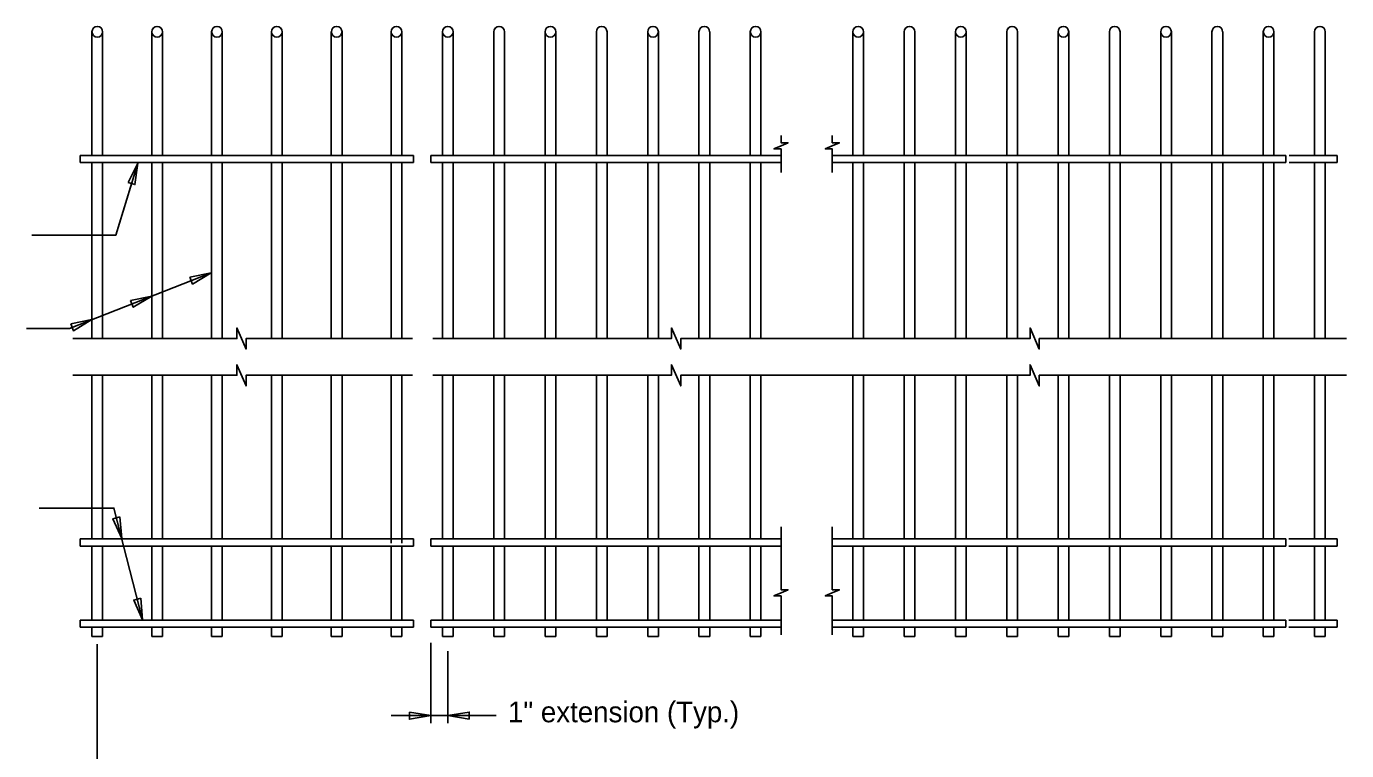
# Model space of a CAD drawing. Extents: x 4.6 to 40.7, y -0.7 to 17.4.
# Drawn here: x 8.02 to 14.45, y 7.29 to 10.82 of the extents above; entities that cross this region are included whole.
import ezdxf

# ---------------------------------------------------------------- set-up
doc = ezdxf.new("R2010")
doc.units = 0
for name, color, linetype in [('Dimension', 7, 'Continuous'), ('Rebar', 7, 'Continuous'), ('Rebar_h', 7, 'Continuous'), ('Symbols', 7, 'Continuous')]:
    doc.layers.add(name, color=color, linetype=linetype)

msp = doc.modelspace()

# ---------------------------------------------------------------- linework, layer by layer
at = {"layer": 'Dimension'}
for p, q in [((8.3629, 6.3332), (8.3629, 7.8082)), ((9.9879, 7.8157), (9.9879, 7.4242)), ((10.0712, 7.7749), (10.0712, 7.4242)), ((9.7947, 7.4608), (10.3061, 7.4608))]:
    msp.add_line(p, q, dxfattribs=at)
for points in [[(11.6949, 10.287), (11.6949, 10.2513), (11.7293, 10.2513), (11.6949, 10.2363), (11.6604, 10.2213), (11.6949, 10.2213), (11.6949, 10.1072)], [(11.9448, 10.287), (11.9448, 10.2513), (11.9793, 10.2513), (11.9448, 10.2363), (11.9104, 10.2213), (11.9448, 10.2213), (11.9448, 10.1072)], [(8.0433, 9.801), (8.4532, 9.801), (8.56, 10.1525)], [(8.0175, 9.347), (8.2271, 9.347), (8.9178, 9.6176)], [(8.0798, 8.4721), (8.4443, 8.4721), (8.5831, 7.9274)], [(11.6949, 8.3812), (11.6949, 8.0739), (11.7293, 8.0739), (11.6949, 8.0589), (11.6604, 8.0439), (11.6949, 8.0439), (11.6949, 7.8542)], [(11.9448, 8.3812), (11.9448, 8.0739), (11.9793, 8.0739), (11.9448, 8.0589), (11.9104, 8.0439), (11.9448, 8.0439), (11.9448, 7.8542)]]:
    msp.add_lwpolyline(points, dxfattribs=at)
for points in [[(8.5128, 10.058), (8.56, 10.1525), (8.5466, 10.0478)], [(8.8144, 9.596), (8.9178, 9.6176), (8.8273, 9.5632)], [(8.5251, 9.4827), (8.6285, 9.5043), (8.538, 9.4499)], [(8.2335, 9.3685), (8.3369, 9.39), (8.2463, 9.3356)], [(8.4734, 8.4285), (8.482, 8.3232), (8.4392, 8.4198)], [(8.5745, 8.0327), (8.5831, 7.9274), (8.5403, 8.024)], [(9.8838, 7.4784), (9.9879, 7.4608), (9.8838, 7.4431)], [(10.1754, 7.4431), (10.0712, 7.4608), (10.1754, 7.4784)]]:
    msp.add_lwpolyline(points, close=True, dxfattribs=at)
at = {"layer": 'Rebar'}
for p, q in [((8.3369, 10.792), (8.3369, 10.1898)), ((8.3889, 10.792), (8.3889, 10.1898)), ((8.6285, 10.792), (8.6285, 10.1898)), ((8.6806, 10.792), (8.6806, 10.1898)), ((8.9202, 10.792), (8.9202, 10.1898)), ((8.9723, 10.792), (8.9723, 10.1898)), ((9.2119, 10.792), (9.2119, 10.1898)), ((9.2639, 10.792), (9.2639, 10.1898)), ((9.5035, 10.792), (9.5035, 10.1898)), ((9.5556, 10.792), (9.5556, 10.1898)), ((9.7952, 10.792), (9.7952, 10.1898)), ((9.8473, 10.792), (9.8473, 10.1898)), ((10.0452, 10.792), (10.0452, 10.1898)), ((10.0973, 10.792), (10.0973, 10.1898)), ((10.5452, 10.792), (10.5452, 10.1898)), ((10.5973, 10.792), (10.5973, 10.1898)), ((11.0452, 10.792), (11.0452, 10.1898)), ((11.0973, 10.792), (11.0973, 10.1898)), ((11.5452, 10.792), (11.5452, 10.1898)), ((11.5973, 10.792), (11.5973, 10.1898)), ((12.0452, 10.792), (12.0452, 10.1898)), ((12.0973, 10.792), (12.0973, 10.1898)), ((12.5452, 10.792), (12.5452, 10.1898)), ((12.5973, 10.792), (12.5973, 10.1898)), ((13.0452, 10.792), (13.0452, 10.1898)), ((13.0973, 10.792), (13.0973, 10.1898)), ((13.5452, 10.792), (13.5452, 10.1898)), ((13.5973, 10.792), (13.5973, 10.1898)), ((14.0452, 10.792), (14.0452, 10.1898)), ((14.0973, 10.792), (14.0973, 10.1898)), ((8.2796, 10.1898), (9.9046, 10.1898)), ((8.2796, 10.1898), (8.2796, 10.1547)), ((9.9046, 10.1898), (9.9046, 10.1547)), ((9.9879, 10.1898), (9.9879, 10.1547)), ((9.9879, 10.1898), (11.6949, 10.1898)), ((11.9448, 10.1898), (14.1546, 10.1898)), ((14.1546, 10.1898), (14.1546, 10.1547)), ((8.2796, 10.1547), (9.9046, 10.1547)), ((8.3369, 10.1547), (8.3369, 9.2976)), ((8.3889, 10.1547), (8.3889, 9.2976)), ((8.6285, 10.1547), (8.6285, 9.2976)), ((8.6806, 10.1547), (8.6806, 9.2976)), ((8.9202, 10.1547), (8.9202, 9.2976)), ((8.9723, 10.1547), (8.9723, 9.2976)), ((9.2119, 10.1547), (9.2119, 9.2976)), ((9.2639, 10.1547), (9.2639, 9.2976)), ((9.5035, 10.1547), (9.5035, 9.2976)), ((9.5556, 10.1547), (9.5556, 9.2976)), ((9.7952, 10.1547), (9.7952, 9.2976)), ((9.8473, 10.1547), (9.8473, 9.2976)), ((9.9879, 10.1547), (11.6949, 10.1547)), ((10.0452, 10.1547), (10.0452, 9.2976)), ((10.0973, 10.1547), (10.0973, 9.2976)), ((10.5452, 10.1547), (10.5452, 9.2976)), ((10.5973, 10.1547), (10.5973, 9.2976)), ((11.0452, 10.1547), (11.0452, 9.2976)), ((11.0973, 10.1547), (11.0973, 9.2976)), ((11.5452, 10.1547), (11.5452, 9.2976)), ((11.5973, 10.1547), (11.5973, 9.2976)), ((11.9448, 10.1547), (14.1546, 10.1547)), ((12.0452, 10.1547), (12.0452, 9.2976)), ((12.0973, 10.1547), (12.0973, 9.2976)), ((12.5452, 10.1547), (12.5452, 9.2976)), ((12.5973, 10.1547), (12.5973, 9.2976)), ((13.0452, 10.1547), (13.0452, 9.2976)), ((13.0973, 10.1547), (13.0973, 9.2976)), ((13.5452, 10.1547), (13.5452, 9.2976)), ((13.5973, 10.1547), (13.5973, 9.2976)), ((14.0452, 10.1547), (14.0452, 9.2976)), ((14.0973, 10.1547), (14.0973, 9.2976)), ((8.3369, 9.1186), (8.3369, 8.322)), ((8.3889, 9.1186), (8.3889, 8.322)), ((8.6285, 9.1186), (8.6285, 8.322)), ((8.6806, 9.1186), (8.6806, 8.322)), ((8.9202, 9.1186), (8.9202, 8.322)), ((8.9723, 9.1186), (8.9723, 8.322)), ((9.2119, 9.1186), (9.2119, 8.322)), ((9.2639, 9.1186), (9.2639, 8.322)), ((9.5035, 9.1186), (9.5035, 8.322)), ((9.5556, 9.1186), (9.5556, 8.322)), ((9.7952, 9.1186), (9.7952, 8.3012)), ((9.8473, 9.1186), (9.8473, 8.3012)), ((10.0452, 9.1186), (10.0452, 8.322)), ((10.0973, 9.1186), (10.0973, 8.322)), ((10.5452, 9.1186), (10.5452, 8.322)), ((10.5973, 9.1186), (10.5973, 8.322)), ((11.0452, 9.1186), (11.0452, 8.322)), ((11.0973, 9.1186), (11.0973, 8.322)), ((11.5452, 9.1186), (11.5452, 8.322)), ((11.5973, 9.1186), (11.5973, 8.322)), ((12.0452, 9.1186), (12.0452, 8.322)), ((12.0973, 9.1186), (12.0973, 8.322)), ((12.5452, 9.1186), (12.5452, 8.322)), ((12.5973, 9.1186), (12.5973, 8.322)), ((13.0452, 9.1186), (13.0452, 8.322)), ((13.0973, 9.1186), (13.0973, 8.322)), ((13.5452, 9.1186), (13.5452, 8.322)), ((13.5973, 9.1186), (13.5973, 8.322)), ((14.0452, 9.1186), (14.0452, 8.322)), ((14.0973, 9.1186), (14.0973, 8.322)), ((8.2796, 8.322), (9.9046, 8.322)), ((8.2796, 8.322), (8.2796, 8.2868)), ((9.9046, 8.322), (9.9046, 8.2868)), ((9.9879, 8.322), (9.9879, 8.2868)), ((9.9879, 8.322), (11.6949, 8.322)), ((11.9448, 8.322), (14.1546, 8.322)), ((14.1546, 8.322), (14.1546, 8.2868)), ((8.2796, 8.2868), (9.9046, 8.2868)), ((8.3369, 8.2868), (8.3369, 7.9262)), ((8.3889, 8.2868), (8.3889, 7.9262)), ((8.6285, 8.2868), (8.6285, 7.9262)), ((8.6806, 8.2868), (8.6806, 7.9262)), ((8.9202, 8.2868), (8.9202, 7.9262)), ((8.9723, 8.2868), (8.9723, 7.9262)), ((9.2119, 8.2868), (9.2119, 7.9262)), ((9.2639, 8.2868), (9.2639, 7.9262)), ((9.5035, 8.2868), (9.5035, 7.9262)), ((9.5556, 8.2868), (9.5556, 7.9262)), ((9.7952, 8.2868), (9.7952, 7.9262)), ((9.8473, 8.2868), (9.8473, 7.9262)), ((9.9879, 8.2868), (11.6949, 8.2868)), ((10.0452, 8.2868), (10.0452, 7.9262)), ((10.0973, 8.2868), (10.0973, 7.9262)), ((10.5452, 8.2868), (10.5452, 7.9262)), ((10.5973, 8.2868), (10.5973, 7.9262)), ((11.0452, 8.2868), (11.0452, 7.9262)), ((11.0973, 8.2868), (11.0973, 7.9262)), ((11.5452, 8.2868), (11.5452, 7.9262)), ((11.5973, 8.2868), (11.5973, 7.9262)), ((11.9448, 8.2868), (14.1546, 8.2868)), ((12.0452, 8.2868), (12.0452, 7.9262)), ((12.0973, 8.2868), (12.0973, 7.9262)), ((12.5452, 8.2868), (12.5452, 7.9262)), ((12.5973, 8.2868), (12.5973, 7.9262)), ((13.0452, 8.2868), (13.0452, 7.9262)), ((13.0973, 8.2868), (13.0973, 7.9262)), ((13.5452, 8.2868), (13.5452, 7.9262)), ((13.5973, 8.2868), (13.5973, 7.9262)), ((14.0452, 8.2868), (14.0452, 7.9262)), ((14.0973, 8.2868), (14.0973, 7.9262)), ((14.0973, 8.2868), (14.0973, 7.9262)), ((8.2796, 7.9262), (9.9046, 7.9262)), ((8.2796, 7.9262), (8.2796, 7.891)), ((9.9046, 7.9262), (9.9046, 7.891)), ((9.9879, 7.9262), (9.9879, 7.891)), ((9.9879, 7.9262), (11.6949, 7.9262)), ((11.9448, 7.9262), (14.1546, 7.9262)), ((14.1546, 7.9262), (14.1546, 7.891)), ((8.2796, 7.891), (9.9046, 7.891)), ((8.3369, 7.891), (8.3369, 7.8461)), ((8.3889, 7.891), (8.3889, 7.8461)), ((8.6285, 7.891), (8.6285, 7.8461)), ((8.6806, 7.891), (8.6806, 7.8461)), ((8.9202, 7.891), (8.9202, 7.8461)), ((8.9723, 7.891), (8.9723, 7.8461)), ((9.2119, 7.891), (9.2119, 7.8461)), ((9.2639, 7.891), (9.2639, 7.8461)), ((9.5035, 7.891), (9.5035, 7.8461)), ((9.5556, 7.891), (9.5556, 7.8461)), ((9.7952, 7.891), (9.7952, 7.8461)), ((9.8473, 7.891), (9.8473, 7.8461)), ((9.9879, 7.891), (11.6949, 7.891)), ((10.0452, 7.891), (10.0452, 7.8461)), ((10.0973, 7.891), (10.0973, 7.8461)), ((10.5452, 7.891), (10.5452, 7.8461)), ((10.5973, 7.891), (10.5973, 7.8461)), ((11.0452, 7.891), (11.0452, 7.8461)), ((11.0973, 7.891), (11.0973, 7.8461)), ((11.5452, 7.891), (11.5452, 7.8461)), ((11.5973, 7.891), (11.5973, 7.8461)), ((11.9448, 7.891), (14.1546, 7.891)), ((12.0452, 7.891), (12.0452, 7.8461)), ((12.0973, 7.891), (12.0973, 7.8461)), ((12.5452, 7.891), (12.5452, 7.8461)), ((12.5973, 7.891), (12.5973, 7.8461)), ((13.0452, 7.891), (13.0452, 7.8461)), ((13.0973, 7.891), (13.0973, 7.8461)), ((13.5452, 7.891), (13.5452, 7.8461)), ((13.5973, 7.891), (13.5973, 7.8461)), ((14.0452, 7.891), (14.0452, 7.8461)), ((14.0973, 7.891), (14.0973, 7.8461)), ((14.1546, 7.891), (14.1546, 7.891)), ((8.3369, 7.8461), (8.3889, 7.8461)), ((8.6806, 7.8461), (8.6285, 7.8461)), ((8.9202, 7.8461), (8.9723, 7.8461)), ((9.2119, 7.8461), (9.2639, 7.8461)), ((9.5035, 7.8461), (9.5556, 7.8461)), ((9.7952, 7.8461), (9.8473, 7.8461)), ((10.0452, 7.8461), (10.0973, 7.8461)), ((10.5452, 7.8461), (10.5973, 7.8461)), ((11.0452, 7.8461), (11.0973, 7.8461)), ((11.5452, 7.8461), (11.5973, 7.8461)), ((12.0452, 7.8461), (12.0973, 7.8461)), ((12.5452, 7.8461), (12.5973, 7.8461)), ((13.0452, 7.8461), (13.0973, 7.8461)), ((13.5452, 7.8461), (13.5973, 7.8461)), ((14.0452, 7.8461), (14.0973, 7.8461))]:
    msp.add_line(p, q, dxfattribs=at)
for centre in [(8.3629, 10.792), (8.6546, 10.792), (8.9462, 10.792), (9.2379, 10.792), (9.5296, 10.792), (9.8212, 10.792), (10.0712, 10.792), (10.5712, 10.792), (11.0712, 10.792), (11.5712, 10.792), (12.0712, 10.792), (12.5712, 10.792), (13.0712, 10.792), (13.5712, 10.792), (14.0712, 10.792)]:
    msp.add_circle(centre, 0.026, dxfattribs=at)
at = {"layer": 'Rebar_h'}
for p, q in [((10.2952, 10.792), (10.2952, 10.1898)), ((10.3473, 10.792), (10.3473, 10.1898)), ((10.7952, 10.792), (10.7952, 10.1898)), ((10.8473, 10.792), (10.8473, 10.1898)), ((11.2952, 10.792), (11.2952, 10.1898)), ((11.3473, 10.792), (11.3473, 10.1898)), ((12.2952, 10.792), (12.2952, 10.1898)), ((12.3473, 10.792), (12.3473, 10.1898)), ((12.7952, 10.792), (12.7952, 10.1898)), ((12.8473, 10.792), (12.8473, 10.1898)), ((13.2952, 10.792), (13.2952, 10.1898)), ((13.3473, 10.792), (13.3473, 10.1898)), ((13.7952, 10.792), (13.7952, 10.1898)), ((13.8473, 10.792), (13.8473, 10.1898)), ((14.2952, 10.792), (14.2952, 10.1898)), ((14.3473, 10.792), (14.3473, 10.1898)), ((14.1711, 10.1898), (14.4046, 10.1898)), ((14.4046, 10.1898), (14.4046, 10.1547)), ((10.2952, 10.1547), (10.2952, 9.2976)), ((10.3473, 10.1547), (10.3473, 9.2976)), ((10.7952, 10.1547), (10.7952, 9.2976)), ((10.8473, 10.1547), (10.8473, 9.2976)), ((11.2952, 10.1547), (11.2952, 9.2976)), ((11.3473, 10.1547), (11.3473, 9.2976)), ((12.2952, 10.1547), (12.2952, 9.2976)), ((12.3473, 10.1547), (12.3473, 9.2976)), ((12.7952, 10.1547), (12.7952, 9.2976)), ((12.8473, 10.1547), (12.8473, 9.2976)), ((13.2952, 10.1547), (13.2952, 9.2976)), ((13.3473, 10.1547), (13.3473, 9.2976)), ((13.7952, 10.1547), (13.7952, 9.2976)), ((13.8473, 10.1547), (13.8473, 9.2976)), ((14.1711, 10.1547), (14.4046, 10.1547)), ((14.2952, 10.1547), (14.2952, 9.2976)), ((14.3473, 10.1547), (14.3473, 9.2976)), ((10.2952, 9.1186), (10.2952, 8.322)), ((10.3473, 9.1186), (10.3473, 8.322)), ((10.7952, 9.1186), (10.7952, 8.322)), ((10.8473, 9.1186), (10.8473, 8.322)), ((11.2952, 9.1186), (11.2952, 8.322)), ((11.3473, 9.1186), (11.3473, 8.322)), ((12.2952, 9.1186), (12.2952, 8.322)), ((12.3473, 9.1186), (12.3473, 8.322)), ((12.7952, 9.1186), (12.7952, 8.322)), ((12.8473, 9.1186), (12.8473, 8.322)), ((13.2952, 9.1186), (13.2952, 8.322)), ((13.3473, 9.1186), (13.3473, 8.322)), ((13.7952, 9.1186), (13.7952, 8.322)), ((13.8473, 9.1186), (13.8473, 8.322)), ((14.2952, 9.1186), (14.2952, 8.322)), ((14.3473, 9.1186), (14.3473, 8.322)), ((14.1699, 8.322), (14.4046, 8.322)), ((14.4046, 8.322), (14.4046, 8.2868)), ((10.2952, 8.2868), (10.2952, 7.9262)), ((10.3473, 8.2868), (10.3473, 7.9262)), ((10.7952, 8.2868), (10.7952, 7.9262)), ((10.8473, 8.2868), (10.8473, 7.9262)), ((11.2952, 8.2868), (11.2952, 7.9262)), ((11.3473, 8.2868), (11.3473, 7.9262)), ((12.2952, 8.2868), (12.2952, 7.9262)), ((12.3473, 8.2868), (12.3473, 7.9262)), ((12.7952, 8.2868), (12.7952, 7.9262)), ((12.8473, 8.2868), (12.8473, 7.9262)), ((13.2952, 8.2868), (13.2952, 7.9262)), ((13.3473, 8.2868), (13.3473, 7.9262)), ((13.7952, 8.2868), (13.7952, 7.9262)), ((13.8473, 8.2868), (13.8473, 7.9262)), ((14.1699, 8.2868), (14.4046, 8.2868)), ((14.2952, 8.2868), (14.2952, 7.9262)), ((14.2952, 8.2868), (14.2952, 7.9262)), ((14.3473, 8.2868), (14.3473, 7.9262)), ((14.3473, 8.2868), (14.3473, 7.9262)), ((14.1699, 7.9262), (14.4046, 7.9262)), ((14.4046, 7.9262), (14.4046, 7.891)), ((10.2952, 7.891), (10.2952, 7.8461)), ((10.3473, 7.891), (10.3473, 7.8461)), ((10.7952, 7.891), (10.7952, 7.8461)), ((10.8473, 7.891), (10.8473, 7.8461)), ((11.2952, 7.891), (11.2952, 7.8461)), ((11.3473, 7.891), (11.3473, 7.8461)), ((12.2952, 7.891), (12.2952, 7.8461)), ((12.3473, 7.891), (12.3473, 7.8461)), ((12.7952, 7.891), (12.7952, 7.8461)), ((12.8473, 7.891), (12.8473, 7.8461)), ((13.2952, 7.891), (13.2952, 7.8461)), ((13.3473, 7.891), (13.3473, 7.8461)), ((13.7952, 7.891), (13.7952, 7.8461)), ((13.8473, 7.891), (13.8473, 7.8461)), ((14.1699, 7.891), (14.4046, 7.891)), ((14.2952, 7.891), (14.2952, 7.8461)), ((14.3473, 7.891), (14.3473, 7.8461)), ((10.2952, 7.8461), (10.3473, 7.8461)), ((10.7952, 7.8461), (10.8473, 7.8461)), ((11.2952, 7.8461), (11.3473, 7.8461)), ((12.2952, 7.8461), (12.3473, 7.8461)), ((12.7952, 7.8461), (12.8473, 7.8461)), ((13.2952, 7.8461), (13.3473, 7.8461)), ((13.7952, 7.8461), (13.8473, 7.8461)), ((14.3473, 7.8461), (14.2952, 7.8461))]:
    msp.add_line(p, q, dxfattribs=at)
for centre, start, end in [((10.3212, 10.792), 0.00089, 180), ((10.8212, 10.792), 0.00089, 180), ((11.3212, 10.792), 0.00089, 180), ((12.3212, 10.792), 0, 180), ((12.8212, 10.792), 0, 180), ((13.3212, 10.792), 0.00089, 180), ((13.8212, 10.792), 0.00089, 180), ((14.3212, 10.792), 0, 179.99911)]:
    msp.add_arc(centre, 0.026, start, end, dxfattribs=at)
at = {"layer": 'Symbols'}
for points in [[(9.8991, 9.2976), (9.0881, 9.2976), (9.0881, 9.246), (9.0431, 9.3493), (9.0431, 9.2976), (8.2439, 9.2976)], [(12.1096, 9.2976), (11.2061, 9.2976), (11.2061, 9.246), (11.1612, 9.3493), (11.1612, 9.2976), (9.9979, 9.2976)], [(14.4512, 9.2976), (12.9538, 9.2976), (12.9538, 9.246), (12.9088, 9.3493), (12.9088, 9.2976), (12.1096, 9.2976)], [(9.8991, 9.1186), (9.0881, 9.1186), (9.0881, 9.0669), (9.0431, 9.1703), (9.0431, 9.1186), (8.2439, 9.1186)], [(12.1096, 9.1186), (11.2061, 9.1186), (11.2061, 9.0669), (11.1612, 9.1703), (11.1612, 9.1186), (9.9979, 9.1186)], [(14.4512, 9.1186), (12.9538, 9.1186), (12.9538, 9.0669), (12.9088, 9.1703), (12.9088, 9.1186), (12.1096, 9.1186)]]:
    msp.add_lwpolyline(points, dxfattribs=at)

# ---------------------------------------------------------------- texts
at = {"layer": 'Dimension'}
msp.add_text('1" extension (Typ.)', height=0.1008, dxfattribs=at).set_placement((10.3644, 7.4283))

doc.saveas('drawing.dxf')
